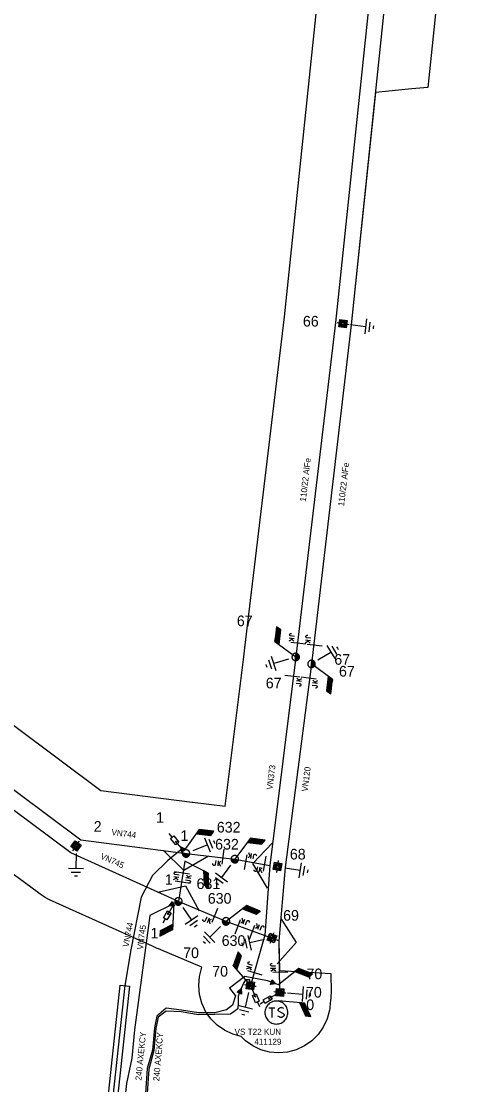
# Model space of a CAD drawing. Extents: x -540879 to -537255, y -1184046 to -1180016.
# Drawn here: x -540110 to -540034.8, y -1183892.2 to -1183717.1 of the extents above; entities that cross this region are included whole.
import ezdxf

# ---------------------------------------------------------------- set-up
doc = ezdxf.new("R2010")
doc.units = 0
for name, color, linetype in [('Default', 7, 'Continuous'), ('Vrstva 1', 7, 'Continuous'), ('Vrstva 11', 7, 'Continuous'), ('Vrstva 12', 7, 'Continuous'), ('Vrstva 13', 7, 'Continuous'), ('Vrstva 14', 7, 'Continuous'), ('Vrstva 15', 7, 'Continuous'), ('Vrstva 16', 7, 'Continuous'), ('Vrstva 18', 7, 'Continuous'), ('Vrstva 19', 7, 'Continuous'), ('Vrstva 2', 7, 'Continuous'), ('Vrstva 20', 7, 'Continuous'), ('Vrstva 25', 7, 'Continuous'), ('Vrstva 26', 7, 'Continuous'), ('Vrstva 27', 7, 'Continuous'), ('Vrstva 3', 7, 'Continuous'), ('Vrstva 35', 7, 'Continuous'), ('Vrstva 4', 7, 'Continuous'), ('Vrstva 5', 7, 'Continuous'), ('Vrstva 52', 7, 'Continuous'), ('Vrstva 6', 7, 'Continuous'), ('Vrstva 7', 7, 'Continuous')]:
    doc.layers.add(name, color=color, linetype=linetype)

# ---------------------------------------------------------------- blocks, each defined once
blk = doc.blocks.new('VN840')
at = {"layer": 'Vrstva 15'}
for points in [[(-0.01, 1.41), (-0.01, -1.09)], [(-1.51, -1.24), (-1.51, -1.15)], [(-1.48, -1.35), (-1.51, -1.24)], [(-1.33, -1.42), (-1.48, -1.35)], [(-1.27, -1.42), (-1.33, -1.42)], [(-1.13, -1.35), (-1.27, -1.42)], [(-1.09, -1.24), (-1.13, -1.35)], [(-1.09, -0.59), (-1.09, -1.24)], [(-0.68, -0.59), (-0.68, -1.42)], [(-0.68, -1.11), (-0.27, -0.59)], [(-0.54, -0.94), (-0.2, -1.42)]]:
    blk.add_lwpolyline(points, dxfattribs=at)
blk = doc.blocks.new('VN860')
at = {"layer": 'Vrstva 15'}
for points in [[(-3.74, 0), (0.01, 2.82)], [(0.01, 2.82), (3.76, 0)]]:
    blk.add_lwpolyline(points, dxfattribs=at)
blk = doc.blocks.new('VN440')
at = {"layer": 'Vrstva 2'}
for points in [[(1.22, 0), (1.21, 0.13), (1.19, 0.25), (1.16, 0.38), (1.11, 0.5), (1.05, 0.61), (0.98, 0.72), (0.9, 0.82), (0.81, 0.91), (0.71, 0.99), (0.6, 1.06), (0.49, 1.12), (0.37, 1.16), (0.25, 1.2), (0.12, 1.22), (-0.01, 1.22), (-0.14, 1.22), (-0.26, 1.2), (-0.39, 1.16), (-0.51, 1.12), (-0.62, 1.06), (-0.73, 0.99), (-0.83, 0.91), (-0.92, 0.82), (-1, 0.72), (-1.07, 0.61), (-1.13, 0.5), (-1.18, 0.38), (-1.21, 0.25), (-1.23, 0.13), (-1.24, 0), (-1.23, -0.13), (-1.21, -0.26), (-1.18, -0.38), (-1.13, -0.5), (-1.07, -0.62), (-1, -0.73), (-0.92, -0.83), (-0.83, -0.92), (-0.73, -1), (-0.62, -1.07), (-0.51, -1.13), (-0.39, -1.17), (-0.26, -1.2), (-0.14, -1.23), (-0.01, -1.23), (0.12, -1.23), (0.25, -1.2), (0.37, -1.17), (0.49, -1.13), (0.6, -1.07), (0.71, -1), (0.81, -0.92), (0.9, -0.83), (0.98, -0.73), (1.05, -0.62), (1.11, -0.5), (1.16, -0.38), (1.19, -0.26), (1.21, -0.13), (1.22, 0)], [(-1.24, 0), (1.22, 0)], [(-1.18, -0.34), (1.1, -0.34)], [(-1.01, -0.63), (0.97, -0.63)], [(-0.74, -0.92), (0.68, -0.92)]]:
    blk.add_lwpolyline(points, dxfattribs=at)
blk = doc.blocks.new('VN890')
at = {"layer": 'Vrstva 4'}
for points in [[(-0.41, 0.41), (0.41, 0)], [(-0.41, -0.41), (-0.41, 0.41)], [(0.41, 0), (-0.41, -0.41)], [(-0.34, 0.31), (0.27, 0), (-0.34, -0.3), (-0.34, 0.31)], [(-0.26, 0.2), (0.1, 0), (-0.26, -0.18), (-0.26, 0.2)], [(-0.19, 0.09), (-0.04, 0), (-0.19, -0.08), (-0.19, 0.09)], [(-0.16, -0.01), (-0.16, 0.03), (-0.13, 0.01), (-0.16, -0.01)]]:
    blk.add_lwpolyline(points, dxfattribs=at)
blk = doc.blocks.new('VN820')
at = {"layer": 'Vrstva 13'}
for points in [[(0, 0), (0, -2.1)], [(-0.32, -1.63), (0.34, -1.63)], [(-0.32, -2.95), (-0.32, -1.63)], [(0.34, -1.63), (0.34, -2.95)], [(0.34, -2.95), (-0.32, -2.95)], [(0, -2.1), (-0.12, -1.86)], [(0, -2.1), (0.12, -1.86)], [(0, -2.95), (0, -3.75)]]:
    blk.add_lwpolyline(points, dxfattribs=at)
blk = doc.blocks.new('VN810')
at = {"layer": 'Vrstva 14'}
for points in [[(0, -1.25), (0, -3.75)], [(1.25, -3.75), (-1.25, -3.75)], [(0.77, -4.37), (-0.8, -4.37)], [(0, -5), (-0.25, -5)], [(0.27, -5), (0, -5)]]:
    blk.add_lwpolyline(points, dxfattribs=at)
blk = doc.blocks.new('VN610')
at = {"layer": 'Vrstva 6'}
for points in [[(1.88, 0), (1.87, 0.2), (1.84, 0.39), (1.79, 0.58), (1.72, 0.77), (1.63, 0.94), (1.52, 1.11), (1.4, 1.26), (1.26, 1.4), (1.1, 1.53), (0.94, 1.63), (0.76, 1.72), (0.58, 1.8), (0.39, 1.85), (0.19, 1.88), (-0.01, 1.89), (-0.21, 1.88), (-0.4, 1.85), (-0.59, 1.8), (-0.78, 1.72), (-0.95, 1.63), (-1.12, 1.53), (-1.27, 1.4), (-1.41, 1.26), (-1.54, 1.11), (-1.64, 0.94), (-1.73, 0.77), (-1.8, 0.58), (-1.86, 0.39), (-1.89, 0.2), (-1.9, 0), (-1.89, -0.2), (-1.86, -0.39), (-1.8, -0.58), (-1.73, -0.77), (-1.64, -0.95), (-1.54, -1.11), (-1.41, -1.27), (-1.27, -1.41), (-1.12, -1.53), (-0.95, -1.64), (-0.78, -1.73), (-0.59, -1.8), (-0.4, -1.85), (-0.21, -1.88), (-0.01, -1.89), (0.19, -1.88), (0.39, -1.85), (0.58, -1.8), (0.76, -1.73), (0.94, -1.64), (1.1, -1.53), (1.26, -1.41), (1.4, -1.27), (1.52, -1.11), (1.63, -0.95), (1.72, -0.77), (1.79, -0.58), (1.84, -0.39), (1.87, -0.2), (1.88, 0)], [(-1.27, 0.78), (-0.26, 0.78)], [(-0.76, 0.78), (-0.76, -0.79)], [(1.19, 0.66), (0.94, 0.78), (0.62, 0.78), (0.37, 0.66), (0.24, 0.47), (0.24, 0.4), (0.37, 0.22), (1.12, -0.16), (1.25, -0.32), (1.25, -0.48), (1.12, -0.67), (0.87, -0.79), (0.62, -0.79), (0.49, -0.73), (0.24, -0.6)]]:
    blk.add_lwpolyline(points, dxfattribs=at)
blk = doc.blocks.new('VN001')
at = {"layer": 'Default'}
for p, q in [((2.02, 3.53), (4.43, 3.53)), ((2.05, 3.58), (4.46, 3.58)), ((2.07, 3.63), (4.49, 3.63)), ((2.1, 3.68), (4.52, 3.68)), ((2.13, 3.73), (2.54, 3.73)), ((1.73, 3.03), (4.14, 3.03)), ((1.76, 3.08), (4.17, 3.08)), ((1.79, 3.13), (4.2, 3.13)), ((1.82, 3.18), (4.23, 3.18)), ((1.85, 3.23), (4.26, 3.23)), ((1.87, 3.28), (4.29, 3.28)), ((1.9, 3.33), (4.32, 3.33)), ((1.93, 3.38), (4.35, 3.38)), ((1.96, 3.43), (4.37, 3.43)), ((1.99, 3.48), (4.4, 3.48))]:
    blk.add_line(p, q, dxfattribs=at)
blk.add_lwpolyline([(2.13, 3.73), (0, 0)], dxfattribs=at)
blk.add_lwpolyline([(4.55, 3.73), (2.13, 3.73), (1.7, 2.98), (4.12, 2.99)], close=True, dxfattribs=at)
blk = doc.blocks.new('VN470')
at = {"layer": 'Vrstva 2'}
for points in [[(-1.23, 1.22), (1.23, 1.22)], [(-1.23, -1.23), (-1.23, 1.22)], [(-0.92, 0.9), (0.92, 0.9)], [(-0.92, -0.95), (-0.92, 0.9)], [(-0.61, 0.61), (0.61, 0.61)], [(-0.61, -0.62), (-0.61, 0.61)], [(-0.31, -0.27), (-0.31, 0.34)], [(-0.31, 0.34), (0.31, 0.34)], [(0, 1.22), (0, 1.97)], [(0.31, 0.34), (0.31, -0.27)], [(0.61, 0.61), (0.61, -0.62)], [(0.92, 0.9), (0.92, -0.95)], [(1.23, 1.22), (1.23, -1.23)], [(1.23, -1.23), (-1.23, -1.23)], [(0.92, -0.95), (-0.92, -0.95)], [(0.61, -0.62), (-0.61, -0.62)], [(0.31, -0.27), (-0.31, -0.27)], [(0, -1.23), (0, -1.98)]]:
    blk.add_lwpolyline(points, dxfattribs=at)

msp = doc.modelspace()

# ---------------------------------------------------------------- linework, layer by layer
at = {"layer": 'Vrstva 1'}
for points in [[(-540084.14, -1183862.05), (-540101.85, -1183854.04), (-540159.34, -1183811.21), (-540235.1, -1183754.61), (-540318.87, -1183692.12), (-540400.06, -1183631.69), (-540472.76, -1183579.47), (-540603.37, -1183567.42), (-540704.86, -1183559.14), (-540798.66, -1183550.97), (-540879.38, -1183550.59)], [(-540398.69, -1183629.52), (-540317.37, -1183690.09), (-540233.62, -1183752.5), (-540157.62, -1183809.02), (-540100.23, -1183851.93), (-540082.89, -1183854.15)], [(-540045.72, -1183647.03), (-540058.25, -1183766.71), (-540064.83, -1183821.78)], [(-540043.23, -1183647.3), (-540055.69, -1183767.11), (-540062.23, -1183822.93)], [(-540064.83, -1183821.78), (-540069.07, -1183856.15)], [(-540062.23, -1183822.93), (-540066.59, -1183856.47), (-540067.58, -1183868.57)], [(-540082.89, -1183854.15), (-540074.86, -1183855.1)], [(-540074.86, -1183855.1), (-540069.07, -1183856.15)], [(-540069.07, -1183856.15), (-540069.9, -1183867.59), (-540072.3, -1183875.92)], [(-540076.3, -1183865.34), (-540084.14, -1183862.05)], [(-540067.58, -1183868.57), (-540076.3, -1183865.34)], [(-540067.58, -1183868.57), (-540067.48, -1183877.05)]]:
    msp.add_lwpolyline(points, dxfattribs=at)
at = {"layer": 'Vrstva 20'}
msp.add_lwpolyline([(-540093.72, -1183875.84), (-540092.22, -1183876), (-540099.23, -1183941.17), (-540100.73, -1183941.01)], close=True, dxfattribs=at)
at = {"layer": 'Vrstva 35'}
for points in [[(-540034.85, -1183648.78), (-540043.08, -1183728.01), (-540045.68, -1183728.23), (-540051.71, -1183728.8), (-540055.69, -1183767.11), (-540062.23, -1183822.93), (-540066.59, -1183856.47), (-540067.58, -1183868.57), (-540067.52, -1183873.42), (-540059.02, -1183873.93), (-540058.98, -1183877), (-540059.12, -1183878.48), (-540059.16, -1183878.71), (-540059.23, -1183879.69), (-540059.28, -1183879.98), (-540059.66, -1183881.41), (-540060.29, -1183882.75), (-540061.14, -1183883.96), (-540062.19, -1183885.01), (-540063.4, -1183885.86), (-540064.74, -1183886.49), (-540066.17, -1183886.87), (-540067.65, -1183887), (-540069.12, -1183886.87), (-540070.56, -1183886.49), (-540071.9, -1183885.86), (-540073.11, -1183885.01), (-540073.79, -1183884.3), (-540075.21, -1183883.91), (-540076.55, -1183883.28), (-540077.77, -1183882.43), (-540078.82, -1183881.38), (-540079.67, -1183880.17), (-540080.01, -1183879.43), (-540080.29, -1183878.83), (-540080.68, -1183877.4), (-540080.8, -1183875.92), (-540080.68, -1183874.44), (-540080.47, -1183873.56), (-540080.28, -1183872.89), (-540087.05, -1183870.04), (-540087.42, -1183869.89), (-540087.64, -1183869.79), (-540088.4, -1183869.43), (-540094.99, -1183866.46), (-540105.36, -1183861.78), (-540106.1, -1183861.4), (-540106.93, -1183860.85), (-540107.43, -1183860.48), (-540113.21, -1183856.18)], [(-540317.37, -1183690.09), (-540243.05, -1183745.47), (-540241.44, -1183739.28), (-540240.74, -1183736.59), (-540228.54, -1183745.68), (-540152.54, -1183802.21), (-540096.93, -1183843.78), (-540081.9, -1183845.71), (-540081.85, -1183845.71), (-540081.81, -1183845.72), (-540076.43, -1183846.35), (-540073.37, -1183821.78), (-540073.27, -1183820.77), (-540073.21, -1183820.31), (-540066.7, -1183765.76), (-540055.3, -1183656.87)]]:
    msp.add_lwpolyline(points, dxfattribs=at)
at = {"layer": 'Vrstva 4'}
msp.add_lwpolyline([(-540067.64, -1183878.43), (-540067.65, -1183878.5)], dxfattribs=at)
at = {"layer": 'Vrstva 5'}
for points in [[(-540083.24, -1183853.72), (-540083.51, -1183853.39), (-540085.89, -1183855.3), (-540088.39, -1183857.77), (-540090.26, -1183861.36), (-540091.97, -1183870.02), (-540092.97, -1183875.92), (-540097.15, -1183914.52), (-540099.98, -1183941.09), (-540109, -1184024.53)], [(-540084.83, -1183862.39), (-540088.84, -1183864.39), (-540091.38, -1183883.23), (-540091.81, -1183887.85), (-540092.67, -1183892.03), (-540094.81, -1183910.88), (-540096.81, -1183921.97), (-540098.27, -1183935.14), (-540098.77, -1183941.17), (-540106.98, -1184024.6)], [(-540067.66, -1183875.78), (-540068.48, -1183875.48), (-540069.48, -1183875.11), (-540073.2, -1183874.44), (-540075.73, -1183876.32), (-540074.76, -1183877.6), (-540075.26, -1183879.12), (-540076.2, -1183879.92), (-540078.13, -1183880.43), (-540080.82, -1183880.43), (-540083.64, -1183879.97), (-540086.19, -1183879.65), (-540087.7, -1183880.98), (-540088.08, -1183882.88), (-540088.44, -1183886.57), (-540089.31, -1183889.55), (-540089.56, -1183893.63)], [(-540072.3, -1183875.92), (-540072.39, -1183874.96), (-540073.07, -1183874.95), (-540073.4, -1183875.53), (-540073.95, -1183876.79), (-540074.33, -1183877.66), (-540074.32, -1183878.63), (-540074.38, -1183879.73), (-540075.56, -1183880.64), (-540080.83, -1183880.73), (-540083.68, -1183880.22), (-540086.19, -1183880.15), (-540087.47, -1183881.14), (-540087.87, -1183882.96), (-540088.21, -1183886.63), (-540089, -1183889.66), (-540089.32, -1183893.65)]]:
    msp.add_lwpolyline(points, dxfattribs=at)
at = {"layer": 'Vrstva 52'}
msp.add_lwpolyline([(-540083.07, -1183855.41), (-540084.14, -1183862.05)], dxfattribs=at)

# ---------------------------------------------------------------- block references
at = {"layer": 'Vrstva 11'}
for p, rotation in [((-540064.83, -1183821.79), 82.97227774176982), ((-540062.24, -1183822.93), -96.68660830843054), ((-540083.24, -1183853.72), -5.999733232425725), ((-540074.86, -1183855.09), -7.101947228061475), ((-540083.07, -1183855.4), -87.72943615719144), ((-540084.83, -1183862.39), -153.43188067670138), ((-540076.3, -1183865.34), -22.750372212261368), ((-540072.3, -1183875.92), 70.46426947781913), ((-540067.66, -1183875.78), -21.324651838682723), ((-540067.64, -1183878.43), -65.32766515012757)]:
    msp.add_blockref('VN001', p, dxfattribs=dict(at, rotation=rotation))
at = {"layer": 'Vrstva 13'}
for name, p, xscale, yscale, rotation in [('VN470', (-540057.03, -1183766.9), 0.5, 0.49999999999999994, 83.11526105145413), ('VN440', (-540064.83, -1183821.79), 0.5, 0.5000000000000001, 83.18003612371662), ('VN440', (-540062.23, -1183822.93), 0.5000000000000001, 0.5, 83.31339162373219), ('VN470', (-540101, -1183852.91), 0.5, 0.5, -36.70481391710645), ('VN440', (-540082.89, -1183854.15), 0.5000000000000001, 0.5, -7.29050283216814), ('VN440', (-540074.86, -1183855.1), 0.49999999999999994, 0.49999999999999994, -9.332689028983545), ('VN470', (-540067.82, -1183856.31), 0.5, 0.5, -9.787200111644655), ('VN440', (-540084.14, -1183862.05), 0.49999999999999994, 0.5000000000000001, -24.336652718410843), ('VN440', (-540076.3, -1183865.34), 0.5000000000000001, 0.4999999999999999, -22.742711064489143), ('VN470', (-540068.73, -1183868.08), 0.5, 0.5, -19.910569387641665), ('VN470', (-540072.3, -1183875.92), 0.49999999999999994, 0.5000000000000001, 83.7276794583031), ('VN470', (-540067.43, -1183877.04), 0.49999999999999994, 0.5000000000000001, 85.55201129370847)]:
    msp.add_blockref(name, p, dxfattribs=dict(at, xscale=xscale, yscale=yscale, rotation=rotation))
at = {"layer": 'Vrstva 15'}
for p, rotation in [((-540057.03, -1183766.9), 83.11526113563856), ((-540062.24, -1183822.93), 121.15838890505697), ((-540064.84, -1183821.78), -72.80636665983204), ((-540082.89, -1183854.15), 111.85910001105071), ((-540101, -1183852.91), -0.40961389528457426), ((-540074.86, -1183855.09), -35.751658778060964), ((-540067.82, -1183856.31), 80.62684993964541), ((-540084.14, -1183862.05), 35.055088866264), ((-540076.3, -1183865.34), -45.93649661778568), ((-540068.73, -1183868.08), -77.77036665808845), ((-540067.43, -1183877.04), 85.7612873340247), ((-540072.29, -1183875.85), -13.4590577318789)]:
    msp.add_blockref('VN810', p, dxfattribs=dict(at, rotation=rotation))
at = {"layer": 'Vrstva 16'}
for p, rotation in [((-540083.24, -1183853.72), -139.15197230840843), ((-540084.83, -1183862.39), -30.549394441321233), ((-540072.3, -1183875.92), 23.304758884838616), ((-540067.48, -1183877.05), -59.41805263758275)]:
    msp.add_blockref('VN820', p, dxfattribs=dict(at, rotation=rotation))
at = {"layer": 'Vrstva 18'}
for name, p, rotation in [('VN840', (-540064.57, -1183819.55), -96.81996392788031), ('VN840', (-540061.88, -1183819.86), -96.68660839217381), ('VN840', (-540065.22, -1183824.94), 82.97227774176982), ('VN840', (-540062.54, -1183825.26), 82.60627224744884), ('VN860', (-540082.89, -1183854.15), 172.70949730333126), ('VN840', (-540076.84, -1183854.86), -6.709422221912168), ('VN860', (-540069.07, -1183856.15), 83.47401392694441), ('VN840', (-540073.02, -1183855.43), 169.69515281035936), ('VN840', (-540069.97, -1183855.98), -10.304847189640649), ('VN840', (-540083.63, -1183858.9), -99.17129168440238), ('VN840', (-540083.38, -1183857.35), 80.82870831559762), ('VN860', (-540084.14, -1183862.05), -24.33591103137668), ('VN840', (-540078.23, -1183864.53), -22.747369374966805), ('VN840', (-540074.32, -1183866.07), 159.6336333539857), ('VN840', (-540071.93, -1183866.96), 159.6336333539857), ('VN860', (-540067.58, -1183868.57), -94.68643888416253), ('VN840', (-540071.69, -1183873.8), -106.12612222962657), ('VN840', (-540067.52, -1183873.77), -88.7345583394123)]:
    msp.add_blockref(name, p, dxfattribs=dict(at, rotation=rotation))
at = {"layer": 'Vrstva 19'}
for p, rotation in [((-540083.51, -1183853.39), 129.20720282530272), ((-540085.32, -1183862.62), -153.54718882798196), ((-540073.95, -1183876.79), 66.41296956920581), ((-540068.48, -1183875.48), -20.21026897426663)]:
    msp.add_blockref('VN890', p, dxfattribs=dict(at, rotation=rotation))
at = {"layer": 'Vrstva 25'}
msp.add_blockref('VN610', (-540068, -1183880.36), dxfattribs=at)

# ---------------------------------------------------------------- texts
at = {"layer": 'Vrstva 12'}
for s, p in [('67', (-540074.52, -1183816.72)), ('67', (-540057.7, -1183825.02)), ('1', (-540087.83, -1183849.11)), ('632', (-540077.82, -1183850.71)), ('631', (-540081.16, -1183860.01)), ('630', (-540079.31, -1183862.43)), ('1', (-540088.74, -1183868.16)), ('70', (-540083.37, -1183871.39)), ('70', (-540063.06, -1183874.87)), ('0', (-540063.09, -1183879.95))]:
    msp.add_text(s, height=1.75, dxfattribs=at).set_placement(p)
at = {"layer": 'Vrstva 14'}
for s, p in [('66', (-540063.64, -1183767.37)), ('67', (-540058.47, -1183823.07)), ('67', (-540069.76, -1183826.96)), ('2', (-540098.1, -1183850.58)), ('1', (-540083.81, -1183852.1)), ('632', (-540078.1, -1183853.51)), ('68', (-540065.79, -1183855.15)), ('1', (-540086.37, -1183859.32)), ('69', (-540066.9, -1183865.23)), ('630', (-540077.02, -1183869.38)), ('70', (-540078.58, -1183874.44)), ('70', (-540063.14, -1183877.89))]:
    msp.add_text(s, height=1.75, dxfattribs=at).set_placement(p)
at = {"layer": 'Vrstva 2'}
for rotation, p in [(83.18, (-540063.17, -1183796.24)), (83.313, (-540056.87, -1183797.01))]:
    msp.add_text('110/22 AlFe', height=1, rotation=rotation, dxfattribs=at).set_placement(p)
at = {"layer": 'Vrstva 26'}
msp.add_text('411129', height=1, dxfattribs=at).set_placement((-540071.64, -1183885.66))
at = {"layer": 'Vrstva 27'}
msp.add_text('VS T22 KUN', height=1, dxfattribs=at).set_placement((-540074.89, -1183884.03))
at = {"layer": 'Vrstva 3'}
for s, rotation, p in [('VN373', 82.972, (-540068.65, -1183843.7)), ('VN120', 82.606, (-540062.87, -1183844.01)), ('VN744', 352.709, (-540095.22, -1183851.13)), ('VN745', 335.664, (-540097.09, -1183854.97))]:
    msp.add_text(s, height=1, rotation=rotation, dxfattribs=at).set_placement(p)
at = {"layer": 'Vrstva 6'}
for rotation, p in [(84.428, (-540090.25, -1183891.58)), (85.415, (-540087.3, -1183891.69))]:
    msp.add_text('240 AXEKCY', height=1, rotation=rotation, dxfattribs=at).set_placement(p)
at = {"layer": 'Vrstva 7'}
for s, rotation, p in [('VN744', 78.83, (-540092.36, -1183869.64)), ('VN745', 82.322, (-540090, -1183870.05))]:
    msp.add_text(s, height=1, rotation=rotation, dxfattribs=at).set_placement(p)

doc.saveas('drawing.dxf')
